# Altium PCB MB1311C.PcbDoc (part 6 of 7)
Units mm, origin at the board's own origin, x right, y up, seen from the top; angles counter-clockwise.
Board outline 100.03 x 67.03 mm, 6 copper layers (Top Layer, layer2, layer3, layer4, layer5, Bottom Layer), stack 1.208 mm thick; 366 components, 356 nets, 1582 pads, 964 vias.
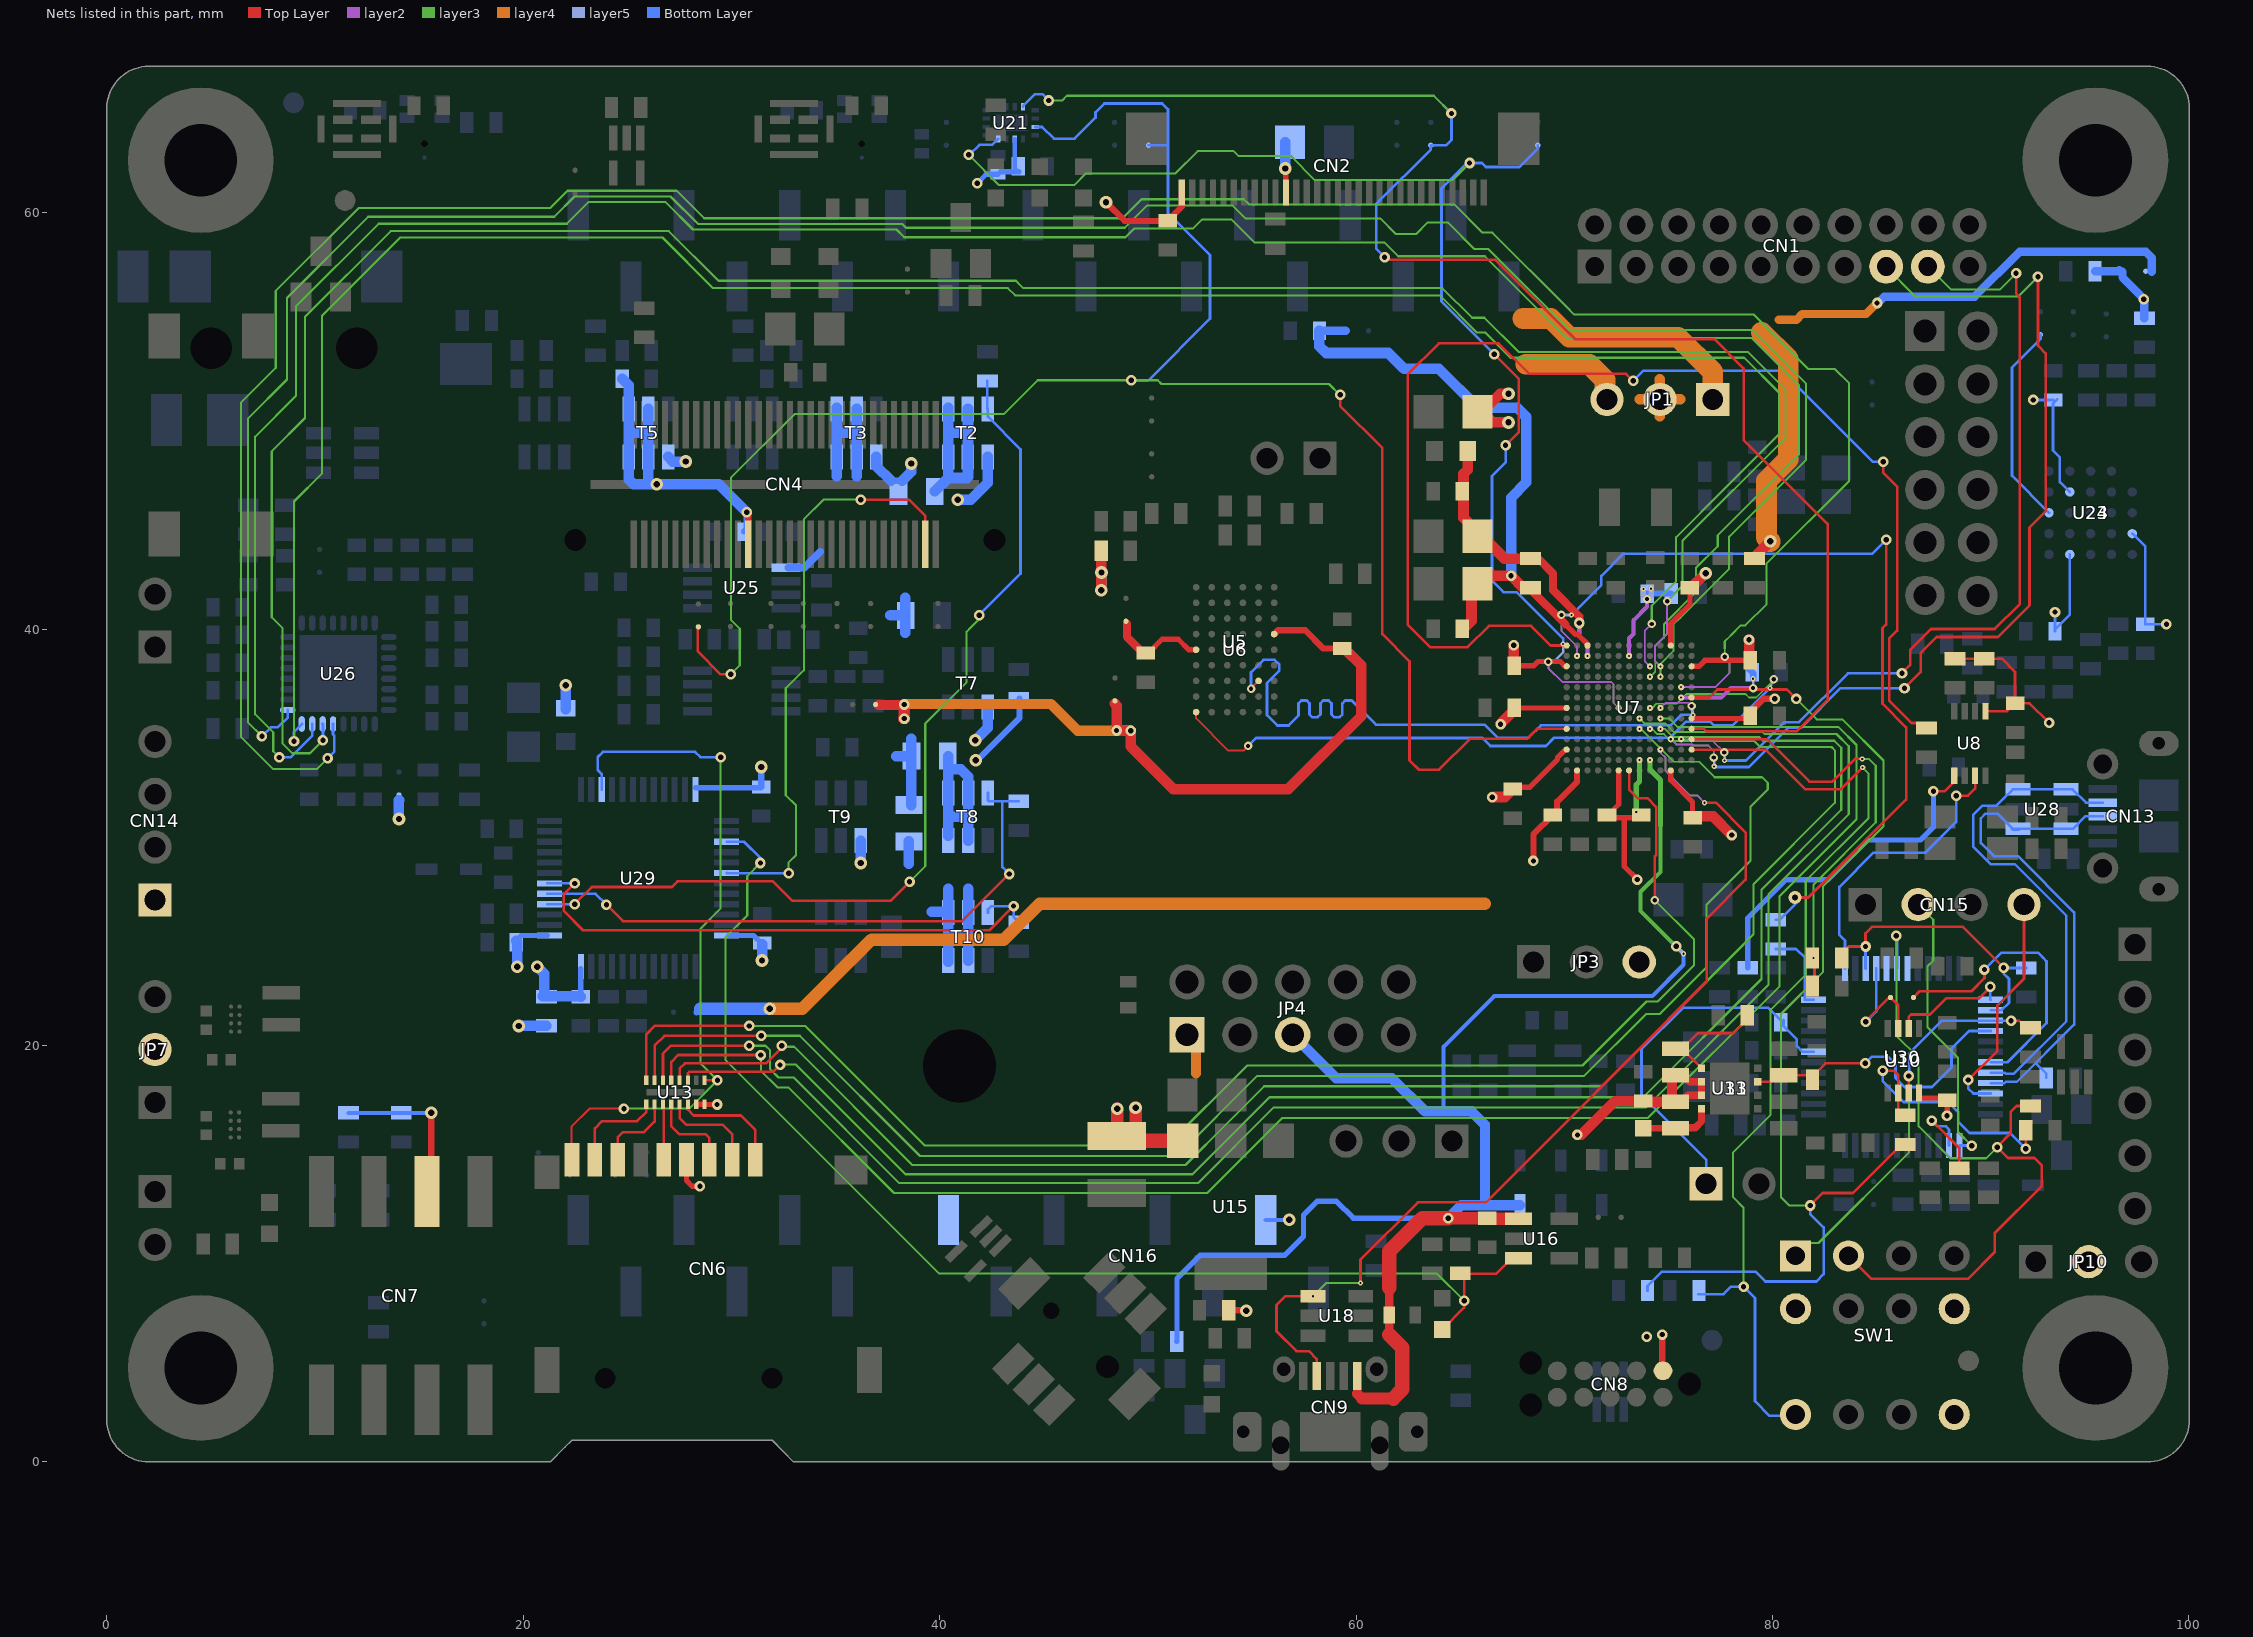
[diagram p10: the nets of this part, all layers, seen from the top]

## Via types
v1: diameter 0.508, hole 0.254, Top Layer to Bottom Layer, tented both sides, 462 vias
v2: diameter 0.61, hole 0.305, Top Layer to Bottom Layer, tented both sides, 126 vias
v3: diameter 0.406, hole 0.203, layer2 to layer5, tented both sides, 109 vias
v4: diameter 0.25, hole 0.1, Top Layer to layer2, tented both sides, 80 vias
v5: diameter 0.25, hole 0.1, Top Layer to layer3, tented both sides, 78 vias
v6: diameter 0.25, hole 0.1, layer5 to Bottom Layer, tented both sides, 52 vias
v7: diameter 0.406, hole 0.203, Top Layer to Bottom Layer, tented both sides, 48 vias
v8: diameter 0.508, hole 0.254, layer2 to layer5, tented both sides, 4 vias
v9: diameter 0.406, hole 0.203, layer2 to layer5, 3 vias
v10: diameter 0.25, hole 0.1, layer5 to Bottom Layer, tented bottom, 1 vias
v11: diameter 0.25, hole 0.1, Top Layer to layer3, tented top, 1 vias

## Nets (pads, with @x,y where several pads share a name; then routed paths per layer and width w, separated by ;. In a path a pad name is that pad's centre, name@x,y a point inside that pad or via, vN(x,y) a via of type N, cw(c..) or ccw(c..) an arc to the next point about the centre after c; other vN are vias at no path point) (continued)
PSRAM_WAIT: U6.J1 U7.E7 | length 37.3
  Top Layer w0.102: U6.J1@52.319,36.008 52.319,35.71 53.867,34.162 54.594,34.162 v7(54.816,34.384)
  layer3 w0.088: v5(74.117,36.208) v5@74.214,36.208 ; v5@74.22,36.202 74.429,36.411 75.4,36.411 75.875,36.886 78.7,36.886 78.875,36.711 79.221,36.711 v3@80.083,37.573
  layer5 w0.127: v6(79.878,37.165) v3(80.068,37.588)
  Bottom Layer w0.127: v7(54.816,34.384) 55.2,34.768 66.064,34.768 66.448,34.384 69.116,34.384 69.51,34.778 75.074,34.778 75.847,35.551 77.008,35.551 77.177,35.381 78.094,35.381 v6(79.878,37.165)
PSRAM_WE: U5.G5 U6.G5 U7.D7 | length 33.1
  Top Layer w0.102: v7(54.959,37.128) 54.959,37.148 U5.G5@55.319,37.508
  layer2 w0.088: v4(74.617,36.208) 74.866,36.457 75.965,36.457 v3(76.118,36.304)
  layer5 w0.127: v3(76.118,36.304) v6(76.188,35.878)
  Bottom Layer w0.127: v7(54.959,37.128) 54.959,37.923 55.553,38.517 56.095,38.517 56.316,38.296 56.316,37.999 55.727,37.41 55.727,35.861 56.221,35.367 56.761,35.367 57.238,35.844 57.238,36.434 57.37,36.566 57.634,36.566 57.765,36.434 57.765,35.898 57.897,35.766 58.161,35.766 58.292,35.898 58.292,36.434 58.424,36.566 58.688,36.566 58.819,36.434 58.819,35.898 58.951,35.766 59.215,35.766 59.346,35.898 59.346,36.434 59.478,36.566 59.795,36.566 60.952,35.409 66.181,35.409 66.804,34.786 68.29,34.786 68.877,35.373 75.098,35.373 75.603,35.878 v6(76.188,35.878)
PWR_ENn: R29.2 U11.3 U30.28 U33.3 | length 14.9
  Top Layer w0.127: U33.3@79.293,18.258 79.908,18.258 80.25,18.6 U11.3@80.575,18.6 ; U11.3@80.318,18.568 U11.3@80.543,18.568 81.708,18.568 R29.2@81.923,18.353 81.923,18.523 82.543,19.143 v1(84.453,19.143)
  Bottom Layer w0.127: v1(84.453,19.143) 84.773,19.463 85.543,19.463 85.913,19.093 85.913,18.433 86.343,18.003 87.663,18.003 88.603,18.943 88.603,19.853 89.443,20.693 U30.28@90.483,20.693
SAI1_FSA: U7.D4 U26.1 | length 121.1
  layer3 w0.088: v5(74.617,37.708) 74.617,38.315 75.249,38.947 75.249,40.219 75.572,40.542
  layer3 w0.102: v1(7.453,34.851) 6.777,35.527 6.777,50.107 8.653,51.983 8.653,55.901 12.556,59.804 21.494,59.804 22.467,60.777 27.078,60.777 28.393,59.462 38.197,59.462 38.386,59.273 48.894,59.273 49.967,60.346 54.062,60.346 54.686,59.722 61.157,59.722 61.904,58.975 62.888,58.975 63.443,59.53 63.77,59.53 64.4,59.53 65.675,58.255 66.351,58.255 70.25,54.356 79.04,54.356 81.618,51.778 81.618,48.128 77.922,44.431 77.922,42.892 75.572,40.542
  Bottom Layer w0.127: v1(7.453,34.851) 7.881,35.279 8.21,35.279 8.693,35.761 U26.1@8.693,36.113
SAI1_MCKA: U7.D3 U26.30 | length 116.5
  layer2 w0.088: v4(74.617,38.208) 74.367,38.457 74.367,39.204 74.943,39.78 v3(74.943,41.339)
  layer3 w0.102: v1(10.383,34.653) 9.763,34.033 8.913,34.033 8.433,34.513 8.433,40.053 7.924,40.562 7.924,48.534 9.523,50.133 9.523,54.993 13.639,59.109 26.997,59.109 29.381,56.725 43.667,56.725 43.759,56.634 44.017,56.375 64.147,56.375 65.574,54.948 66.165,54.948 67.802,53.311 78.811,53.311 80.632,51.49 80.632,49.181 75.683,44.232 75.683,42.079 v3(74.943,41.339)
  Bottom Layer w0.127: U26.30@10.363,35.443 U26.30@10.368,35.438 10.383,35.423 v1(10.383,34.653)
SAI1_SCKA: U7.E4 U26.31 | length 121.1
  layer3 w0.088: v5(74.117,37.708) 74.128,37.708 74.373,37.953 74.373,39.165 74.785,39.577 74.785,40.22
  layer3 w0.102: v1(8.284,33.834) 7.994,34.124 7.994,34.398 7.994,35.039 7.123,35.91 7.123,49.233 9.083,51.193 9.083,55.492 13.056,59.465 22.09,59.465 23.131,60.506 26.841,60.506 28.158,59.189 37.93,59.189 38.301,58.818 48.926,58.818 49.337,59.229 52.162,59.229 52.608,59.675 54.015,59.675 55.133,58.557 61.373,58.557 62.027,57.903 66.191,57.903 70.125,53.969 79.016,53.969 81.274,51.711 81.274,48.4 77.375,44.501 77.375,43.979 76.324,42.928 76.324,41.759 74.785,40.22
  Bottom Layer w0.127: v1(8.284,33.834) 8.825,33.834 9.863,34.872 U26.31@9.863,35.438
SAI1_SDA: U7.E3 U26.32 | length 112.5
  layer2 w0.088: v4(74.117,38.208) 73.867,38.457 73.867,39.907 v3(74.206,40.247)
  layer3 w0.102: v1(8.993,34.613) 8.993,46.124 10.343,47.474 10.343,55.059 14.089,58.805 26.689,58.805 29.119,56.375 43.273,56.375 43.625,56.023 64.023,56.023 65.804,54.242 66.206,54.242 67.418,53.03 78.64,53.03 80.313,51.357 80.313,49.356 77.673,46.716 75.373,44.416 75.373,42.293 74.206,41.126 v3(74.206,40.247)
  Bottom Layer w0.127: v1(8.993,34.613) 8.993,35.053 9.373,35.433 U26.32@9.368,35.438 U26.32@9.363,35.443
SAI1_SDB: U7.B5 U26.29 | length 130.3
  layer2 w0.088: v4(75.617,37.208) 77.264,37.208 77.935,37.879 77.935,38.448 v3(77.712,38.672)
  layer3 w0.088: v3(77.712,38.672) 77.712,39.079 ; 77.712,39.403 77.998,39.689
  layer3 w0.102: v1(10.605,33.799) 10.078,33.272 8.001,33.272 6.442,34.831 6.442,50.872 8.113,52.543 8.113,56.239 12.097,60.223 21.297,60.223 22.125,61.051 27.37,61.051 28.694,59.727 48.785,59.727 49.698,60.64 54.616,60.64 54.862,60.394 64.717,60.394 66.072,59.039 66.546,59.039 70.082,55.503 70.486,55.099 79.117,55.099 81.733,52.483 83.002,52.483 83.681,51.804 83.681,47.11 79.722,43.151 79.722,41.195 78.701,40.174 78.483,40.174 77.998,39.689 ; 77.712,39.079 77.712,39.403
  Bottom Layer w0.127: v1(10.605,33.799) 10.931,34.125 10.931,34.874 10.863,34.942 U26.29@10.863,35.443
SD_CLK: CN6.5 U13.11 | length 2.7
  Top Layer w0.127: U13.11@26.738,17.213 26.743,17.208 CN6.5@26.743,14.513
SD_CMD: CN6.3 U13.12 | length 4.2
  Top Layer w0.127: U13.12@27.113,17.172 27.113,16.113 27.488,15.738 28.763,15.738 28.943,15.558 CN6.3@28.943,14.513
SD_D0: CN6.7 U13.10 | length 4
  Top Layer w0.127: CN6.7@24.543,14.513 24.543,15.593 24.788,15.838 25.813,15.838 26.313,16.338 U13.10@26.313,17.172 U13.10@26.313,17.213
SD_D1: CN6.8 U13.9 | length 4.7
  Top Layer w0.127: CN6.8@23.443,14.513 23.443,16.018 23.788,16.363 25.473,16.363 25.913,16.803 U13.9@25.913,17.172
SD_D2: CN6.1 U13.14 | length 5.3
  Top Layer w0.127: U13.14@27.913,17.172 27.913,16.913 28.188,16.638 30.463,16.638 31.143,15.958 CN6.1@31.143,14.513
SD_D3: CN6.2 U13.13 | length 4.8
  Top Layer w0.127: U13.13@27.513,17.172 U13.13@27.513,17.163 ; U13.13@27.538,17.188 U13.13@27.513,17.163 ; CN6.2@30.043,14.513 30.043,15.733 29.588,16.188 27.838,16.188 27.513,16.513 U13.13@27.513,17.163
SH0: R49.2 T2.3 U29.4 | length 45.5
  Top Layer w0.127: v1(22.473,26.783) 23.301,27.611 27.141,27.611 27.413,27.883 31.993,27.883 32.933,26.943 37.643,26.943 v1(38.558,27.858)
  layer3 w0.102: v1(38.558,27.858) 39.313,28.613 39.313,35.463 41.3,37.45 41.3,39.875 41.499,40.074 41.903,40.479 v1(41.903,40.663)
  Bottom Layer w0.127: U29.4@21.171,26.783 v1(22.473,26.783) ; v1(41.903,40.663) 41.903,40.683 43.883,42.663 43.883,48.632 42.313,50.202 T2.3@42.313,50.573 42.293,50.593 R49.2@42.293,51.91
SH0_D: R55.2 T2.1 T2.2 T2.5 T2.6 | length 9.7
  Bottom Layer w0.127: T2.1@40.413,50.573 T2.1@40.413,50.623
  Bottom Layer w0.508: R55.2@39.772,46.613 40.413,47.254 ; T2.1@40.411,50.424 40.411,50.623 40.413,50.623 T2.1@40.413,50.573 40.413,49.44 ; T2.2@41.363,50.573 41.363,49.423 ; 40.413,47.254 41.295,47.254 41.363,47.322 T2.5@41.363,48.273 41.363,49.423 ; 40.413,47.254 40.413,49.44 ; 40.413,49.44 40.43,49.423 41.363,49.423
SH1: R84.2 T8.3 U29.5 | length 29.1
  Top Layer w0.127: v1(23.997,26.763) 24.792,25.968 41.078,25.968 v1(43.343,28.233)
  Bottom Layer w0.127: U29.5@21.171,27.283 23.477,27.283 v1(23.997,26.763) ; T8.3@42.323,32.136 42.323,31.783 42.383,31.723 43.013,31.723 ; v1(43.343,28.233) 43.013,28.563 43.013,31.723 ; R84.2@43.803,31.723 43.013,31.723
SH1_D: R81.2 T8.1 T8.2 T8.5 T8.6 | length 9.4
  Bottom Layer w0.508: R81.2@40.419,33.258 R81.2@40.421,33.258 ; T8.1@40.421,31.987 T8.1@40.421,32.186 ; R81.2@40.421,33.893 R81.2@40.421,33.258 ; T8.6@40.423,30.067 40.423,31.003 ; T8.2@41.371,31.937 41.371,32.904 41.017,33.258 R81.2@40.421,33.258 ; T8.5@41.373,29.836 41.373,30.986 ; T8.2@41.373,32.136 41.373,30.986 ; T8.1@40.421,32.186 R81.2@40.421,33.258 ; T8.1@40.421,32.186 40.423,32.186 T8.1@40.423,32.136 40.423,31.003 ; 40.423,31.003 40.44,30.986 41.373,30.986
SH2: R89.2 T10.3 U29.6 | length 27.6
  Top Layer w0.127: v1(22.473,27.783) 21.953,27.263 21.953,26.463 22.883,25.533 42.393,25.533 v1(43.553,26.693)
  Bottom Layer w0.127: U29.6@21.171,27.783 v1(22.473,27.783) ; T10.3@42.323,26.376 42.323,26.533 42.483,26.693 v1(43.553,26.693) 43.563,26.683 43.563,26.153 R89.2@43.803,25.913
SH2_D: R85.2 T10.1 T10.2 T10.5 T10.6 | length 10.2
  Bottom Layer w0.5: 38.523,28.713 R85.2@38.523,29.798
  Bottom Layer w0.508: 39.613,26.426 T10.1@40.421,26.426 ; T10.1@40.421,26.227 T10.1@40.421,26.426 ; 40.421,27.513 T10.1@40.421,26.426 ; T10.6@40.423,24.026 40.423,25.263 ; T10.2@41.371,26.177 41.371,27.513 ; T10.5@41.373,24.076 41.373,25.263 ; T10.2@41.373,26.376 41.373,25.263 ; T10.1@40.421,26.426 40.423,26.426 T10.1@40.423,26.376 40.423,25.263 ; 40.423,25.263 41.373,25.263
SPI2_MISOs: CN1.9 U7.B10 | length 41.8
  Top Layer w0.127: v1(86.223,37.879) 86.613,38.269 86.613,39.003 87.613,40.003 90.674,40.003 91.882,41.211 91.882,55.934 91.703,56.113 v1(91.703,57.093)
  layer2 w0.088: v4(75.621,34.709) 76.186,34.709 76.281,34.614 77.147,34.614 v3(77.686,34.074)
  layer3 w0.102: CN1.9@87.463,57.813 87.463,57.424 88.587,56.3 90.91,56.3 v1(91.703,57.093)
  layer5 w0.127: v3(77.686,34.074) v6(77.703,33.683)
  Bottom Layer w0.127: v6(77.703,33.683) 78.73,33.683 80.57,35.524 81.285,35.524 83.633,37.871 v1@86.231,37.871
SPI2_MOSIs: CN1.8 U7.C10 | length 46.9
  Top Layer w0.127: v1(86.343,37.159) 87.123,37.939 87.123,38.849 87.888,39.614 90.824,39.614 92.35,41.14 92.35,44.876 93.123,45.649 93.123,53.243 92.753,53.613 v1(92.753,56.913)
  layer2 w0.088: v4(75.117,34.708) 75.122,34.708 75.373,34.457 76.159,34.457 76.217,34.399 76.929,34.399 77.178,34.15 v3(77.178,33.828)
  layer3 w0.102: CN1.8@85.463,57.813 CN1.8@85.463,57.407 85.463,57.37 86.859,55.974 91.814,55.974 v1(92.753,56.913)
  layer5 w0.127: v3(77.178,33.828) v6(77.201,33.406)
  Bottom Layer w0.127: v6(77.201,33.406) 77.234,33.373 78.863,33.373 80.76,35.27 81.39,35.27 83.28,37.159 v1(86.343,37.159)
STL_USB_D_N: CN13.2 U28.1 U28.6 U30.32 | length 24.1
  Bottom Layer w0.122: U30.32@90.483,18.693 91.144,18.693 91.206,18.631 91.588,18.631 94.113,21.156 94.113,26.238 91.638,28.713 90.481,28.713 89.637,29.557 89.637,31.069 90.082,31.514 90.764,31.514 91.128,31.878 91.553,32.303 U28.6@91.803,32.303
  Bottom Layer w0.127: U28.6@91.803,32.303 U28.1@94.103,32.303 94.423,32.303 95.063,31.663 CN13.2@95.863,31.663
STL_USB_D_P: CN13.3 R98.2 U28.3 U28.4 U30.33 | length 25.6
  Bottom Layer w0.122: U30.33@90.483,18.193 91.144,18.193 91.206,18.255 91.744,18.255 94.489,21 94.489,26.394 91.794,29.089 90.637,29.089 90.013,29.713 90.013,30.913 90.238,31.138 90.813,31.138 91.128,30.823 91.548,30.403 U28.4@91.803,30.403 ; 92.659,19.134 93.153,18.64 R98.2@93.153,18.443
  Bottom Layer w0.127: U28.4@91.753,30.403 91.498,30.403 91.538,30.363 U28.4@91.838,30.363 ; U28.4@91.803,30.403 U28.3@94.103,30.403 94.428,30.403 95.038,31.013 CN13.3@95.863,31.013
STLINK_RX: U8.7 U30.13 | length 13.9
  Top Layer w0.127: v1(88.823,31.993) 89.393,31.993 89.733,32.333 U8.7@89.733,32.953
  Bottom Layer w0.127: U30.13@83.483,23.693 83.483,25.043 83.213,25.313 83.213,27.613 84.863,29.263 87.363,29.263 88.823,30.723 v1(88.823,31.993)
STLINK_TX: R88.1 U30.12 | length 4
  Bottom Layer w0.127: R88.1@80.163,24.633 81.133,24.633 81.553,24.213 81.553,22.193 U30.12@81.983,22.193
STM_JTCK: CN15.2 U30.37 | length 13.5
  layer3 w0.102: CN15.2@87.003,26.763 87.723,26.043 87.723,24.073 87.443,23.793 87.443,20.883 88.913,19.413 88.913,15.843 v1(89.573,15.183)
  Bottom Layer w0.127: U30.37@88.983,15.193 89.563,15.193 v1(89.573,15.183)
STM_JTMS: CN15.4 U30.34 | length 11.1
  Top Layer w0.127: v1(89.403,18.343) 90.803,19.743 90.803,21.923 92.083,23.203 CN15.4@92.083,26.763
  Bottom Layer w0.127: v1(89.403,18.343) 89.403,17.943 89.653,17.693 U30.34@90.483,17.693
STM_RST: C92.1 JP8.1 U30.7 | length 18
  Bottom Layer w0.127: JP8.1@76.813,13.353 76.813,14.513 73.713,17.613 73.713,19.823 75.693,21.803 79.803,21.803 C92.1@80.403,21.203 ; C92.1@80.533,21.223 80.533,20.933 81.173,20.293 81.173,19.973 81.453,19.693 U30.7@81.983,19.693
SWCLK: R24.1 R26.2 U7.A10 | length 22.2
  Top Layer w0.127: U7.A10@76.117,34.708 79.735,34.708 81.771,32.673 82.879,32.673 83.97,33.763 v5(84.313,33.763) ; R24.1@81.923,24.193 v5(81.973,24.193) ; R26.2@82.023,22.853 R24.1@82.023,24.233
  layer3 w0.102: v5(81.973,24.193) 81.973,27.723 84.963,30.713 84.963,33.433 84.633,33.763 v5(84.313,33.763)
SWDIO: R110.2 SW1.8 U7.A11 | length 47.6
  Top Layer w0.127: U7.A11@76.117,34.208 79.678,34.208 81.574,32.312 83.302,32.312 v5(84.333,33.343)
  layer3 w0.102: v1(78.613,8.413) 78.613,12.213 78.113,12.713 78.113,14.863 79.913,16.663 79.913,21.713 81.603,23.403 81.603,27.903 84.623,30.923 84.623,33.053 v5(84.333,33.343)
  Bottom Layer w0.127: R110.2@76.443,8.053 77.653,8.053 78.013,8.413 v1(78.613,8.413) 79.16,7.866 79.16,2.915 79.862,2.213 SW1.8@81.088,2.213
SWO: R31.1 R111.2 U7.A6 | length 54
  Top Layer w0.127: U7.A6@76.117,36.708 76.967,36.708 77.356,37.097 80.688,37.097 v1(81.143,36.643) ; v1(81.813,12.313) 82.413,12.913 83.863,12.913 86.193,15.243 R31.1@86.383,15.243
  layer3 w0.102: v1(81.143,36.643) 82.125,35.661 83.355,35.661 85.333,33.683 85.333,30.533 82.423,27.623 82.423,23.523 80.413,21.513 80.413,12.713 80.813,12.313 v1(81.813,12.313)
  Bottom Layer w0.127: R111.2@74.003,8.223 74.003,8.443 74.683,9.123 79.203,9.123 79.663,8.663 82.113,8.663 82.463,9.013 82.463,11.263 81.813,11.913 v1(81.813,12.313)
SWO_MCU: R31.2 R32.2 U10.6 | length 13.1
  Top Layer w0.127: v1(85.293,18.793) 85.823,18.793 86.043,18.573 U10.6@86.043,17.713 R31.2@86.043,16.643 ; R31.2@86.043,16.553 R31.2@86.043,16.643 ; R31.2@86.383,16.643 R31.2@86.043,16.643 ; v1(92.173,15.033) R32.2@92.173,15.923
  Bottom Layer w0.127: v1(85.293,18.793) 85.293,18.283 86.293,17.283 88.443,17.283 88.923,16.803 88.923,16.343 89.473,15.793 91.413,15.793 v1(92.173,15.033)
T50_4: JP1.1 R55.1 T3.4 | length 14.5
  layer4 w1: 68.013,54.913 69.35,54.913 70.252,54.011 75.465,54.011 77.137,52.339 JP1.1@77.137,51.027
  Bottom Layer w0.3: R55.1@37.667,47.123 R55.1@38.203,47.123
  Bottom Layer w0.5: T3.4@36.963,48.273 36.963,47.827 R55.1@37.667,47.123 ; R55.1@38.203,47.123 38.638,47.558 v2(38.638,47.951)
T50_6: R62.1 R81.1 R85.1 T3.1 T3.2 T3.5 T3.6 U25.5 | length 15.8
  Bottom Layer w0.356: U25.5@32.728,42.946 33.506,42.946 34.263,43.703
  Bottom Layer w0.508: T3.1@35.061,50.424 35.061,50.623 35.063,50.623 T3.1@35.063,50.573 35.063,49.44 ; 35.063,47.346 35.063,49.44 ; 36.013,47.346 T3.5@36.013,48.273 36.013,49.423 ; T3.2@36.013,50.573 36.013,49.423 ; 37.642,40.652 R62.1@38.354,40.652 ; 37.922,33.893 R81.1@38.634,33.893 ; 38.354,39.813 R62.1@38.354,40.652 ; 38.354,41.491 R62.1@38.354,40.652 ; R85.1@38.634,31.548 R81.1@38.634,33.893 ; 38.634,34.732 R81.1@38.634,33.893 ; 35.063,49.44 35.08,49.423 36.013,49.423
T_JRST: U30.19
T_JTCK: R24.2 R94.2 U30.15 U30.26 | length 14.7
  Top Layer w0.127: R24.2@83.323,24.193 83.323,24.413 83.663,24.753 v1(84.473,24.753) 84.473,25.383 84.783,25.693 89.143,25.693 v1(91.103,23.733)
  Bottom Layer w0.127: v1(84.473,24.753) 84.473,23.703 U30.15@84.483,23.693 ; U30.26@90.483,21.693 91.013,21.693 91.363,22.043 91.363,23.203 91.103,23.463 v1(91.103,23.733) 91.113,23.723 R94.2@92.193,23.723
T_JTDI: U30.17
T_JTDO: SB14.2 U10.3 U30.16 | length 6.1
  Top Layer w0.127: v1(84.483,21.133) 84.483,21.183 85.603,22.303 SB14.2@85.673,22.303 86.043,21.933 U10.3@86.043,20.813
  Bottom Layer w0.127: v1(84.483,21.133) 84.983,21.633 U30.16@84.983,23.693
T_JTMS: R28.2 SW1.1 U10.7 U30.27 | length 19.7
  Top Layer w0.127: U10.7@86.543,17.713 86.553,17.723 v1(86.553,18.533) ; v1(91.463,21.183) 91.473,21.193 91.833,21.193 92.183,20.843 R28.2@92.393,20.843
  layer3 w0.102: SW1.1@81.113,9.893 81.733,10.513 82.213,10.513 86.553,14.853 v1(86.553,18.533)
  Bottom Layer w0.127: v1(86.553,18.533) 86.563,18.543 86.563,19.613 88.143,21.193 U30.27@90.483,21.193 91.453,21.193 v1(91.463,21.183)
T_NRST: R30.2 SW1.2 U30.18 | length 34.5
  Top Layer w0.127: SW1.2@83.653,9.893 84.753,8.793 89.403,8.793 90.678,10.068 90.678,10.988 92.943,13.253 92.943,14.233 92.583,14.593 91.313,14.593 v1(90.793,15.113) 90.793,15.133 91.443,15.783 91.443,16.813 91.723,17.093 R30.2@92.393,17.093
  layer3 w0.102: v1(85.953,25.273) 85.953,20.473 87.023,19.403 87.023,16.113 88.553,14.583 90.263,14.583 v1(90.793,15.113)
  Bottom Layer w0.127: v1(85.953,25.273) 85.983,25.243 U30.18@85.983,23.693
T_SWDIO_IN: U10.2 U30.25 | length 5.7
  Top Layer w0.127: U10.2@86.543,20.813 86.543,21.363 86.663,21.483 87.563,21.483 88.343,22.263 89.913,22.263 v1(90.463,22.813)
  Bottom Layer w0.127: v1(90.463,22.813) 90.463,22.193 U30.25@90.483,22.193
T_SWO: SB14.1 U30.31 | length 14.1
  Top Layer w0.127: SB14.1@86.773,22.303 87.073,22.603 89.553,22.603 90.183,23.233 v1(90.183,23.643)
  Bottom Layer w0.127: v1(90.183,23.643) 90.993,24.453 92.753,24.453 92.99,24.215 ; U30.31@90.483,19.193 91.283,19.193 93.163,21.073 93.163,24.038 92.988,24.213
TOUCH_INT: CN4.4 U29.30 | length 28.6
  Top Layer w0.127: v1(36.213,46.213) 38.53,46.213 39.313,45.43 CN4.4@39.313,44.073
  layer3 w0.102: v1(32.751,28.265) 32.751,28.791 33.107,29.147 33.107,31.522 32.613,32.016 32.613,37.153 33.48,38.02 33.48,45.267 34.426,46.213 v1(36.213,46.213)
  Bottom Layer w0.127: U29.30@29.771,28.283 29.789,28.265 v1(32.751,28.265)
U5V_ST_LINK: C35.2 JP4.1 U11.6 U11.7 U33.6 U33.7 | length 12.6
  Top Layer w0.35: U11.7@75.175,17.3 75.568,17.3 75.65,17.3 75.958,17.608 U33.7@76.593,17.608 U33.6@76.593,18.258 76.017,18.258 75.675,18.6 U11.6@75.175,18.6
  Top Layer w0.5: v1(70.633,15.703) 70.813,15.703 72.443,17.333 C35.2@73.803,17.333 ; C35.2@73.838,17.298 U11.7@75.343,17.298 75.568,17.298 U11.7@75.568,17.3 ; U11.7@75.175,17.3 U11.6@75.175,18.6
  layer4 w0.5: JP4.1@51.883,20.463 52.313,20.033 52.313,18.663
U11_5: R27.2 U11.5 U33.5 | length 5.4
  Top Layer w0.12: U11.5@75.55,19.775 U11.5@75.726,19.775
  Top Layer w0.127: U11.5@75.568,19.838 75.663,19.838 76.424,20.599 78.139,20.599 78.798,21.258 R27.2@78.798,21.452
  Top Layer w0.13: U11.5@75.726,19.775 U33.5@76.593,18.908
U11_8: LD5.2 U11.8 U33.8 | length 3.7
  Top Layer w0.3: LD5.2@73.798,16.028 U11.8@75.343,16.028 U11.8@75.568,16.028
  Top Layer w0.35: U11.8@75.35,16.05 76.3,16.05 76.593,16.343 U33.8@76.593,16.958
USART2_RX: R88.2 U7.M2 | length 41.5
  Top Layer w0.127: v2(81.083,27.103) 81.72,27.103 86.422,31.805 86.422,35.279 85.284,36.417 85.284,40.038 85.463,40.217 v1(85.463,44.283)
  layer2 w0.088: v3(69.863,40.675) 69.863,39.915 70.617,39.161 v4(70.617,38.708)
  layer5 w0.127: v3(69.863,40.675) 70.337,40.675 v6(70.341,40.679)
  Bottom Layer w0.127: v6(70.341,40.679) 71.783,42.121 71.783,42.55 72.855,43.622 84.802,43.622 v1(85.463,44.283) ; R88.2@80.163,26.033 80.343,26.033 81.083,26.773 v2(81.083,27.103)
USART2_TX: R20.1 U7.N1 | length 61.4
  Top Layer w0.127: U7.N1@70.117,39.208 69.348,39.208 68.403,40.153 66.378,40.153 65.352,39.127 63.563,39.127 62.478,40.212 62.478,52.217 63.984,53.723 66.853,53.723 68.322,52.254 72.976,52.254 v1(73.311,51.919) ; v1(85.326,48.03) 85.326,47.501 85.991,46.836 85.991,39.925 85.604,39.538 85.604,36.572 86.686,35.49 87.006,35.49 87.253,35.243 R20.1@87.403,35.243
  Bottom Layer w0.127: v1(73.311,51.919) 73.798,52.406 80.445,52.406 84.821,48.03 v1(85.326,48.03)
USART3_RTS: SB18.1 U7.A9 U21.12 | length 74.7
  Top Layer w0.127: v1(61.373,57.863) 61.505,57.731 66.704,57.731 70.512,53.923 77.216,53.923 78.62,52.519 78.62,49.071 80.526,47.165 82.649,45.042 82.649,36.583 81.155,35.089 76.824,35.089 76.705,35.208 U7.A9@76.117,35.208
  layer3 w0.102: v1(45.242,65.386) 45.885,65.386 46.114,65.615 63.731,65.615 v1(64.583,64.763)
  Bottom Layer w0.127: U21.12@44.013,65.088 44.013,65.123 44.579,65.689 44.939,65.689 v1(45.242,65.386) ; v1(61.373,57.863) 60.97,58.266 60.97,60.41 63.593,63.033 SB18.1@63.593,63.233 64.327,63.233 64.583,63.489 v1(64.583,64.763)
USART3_RX: SB16.1 U7.H7 U21.4 | length 66.1
  Top Layer w0.127: v1(66.637,53.2) 67.818,52.019 67.818,49.458 v1(67.183,48.823)
  layer2 w0.088: v3(69.238,38.423) 69.238,38.126 69.906,37.458 70.017,37.458 ; 70.322,37.458 70.017,37.458 ; v5(72.617,36.208) 72.366,36.458 72.366,37.339 72.247,37.457 70.018,37.457 70.017,37.458
  layer3 w0.102: v1(41.393,62.783) 42.856,61.32 46.46,61.32 47.017,61.877 51.314,61.877 52.392,62.955 54.12,62.955 54.35,62.725 56.858,62.725 58.021,61.562 64.631,61.562 v1@65.453,62.384
  layer5 w0.127: v3(69.238,38.423) 69.49,38.423 69.946,38.879 v6(69.946,39.282)
  Bottom Layer w0.127: v1(41.393,62.783) 41.443,62.783 41.913,63.253 42.528,63.253 U21.4@42.813,63.538 ; v1(66.637,53.2) 64.107,55.73 64.107,61.16 65.33,62.383 v1(65.453,62.383) 66.043,62.383 66.233,62.193 67.843,62.193 68.733,63.083 SB16.1@68.733,63.233 ; v1(67.183,48.823) 67.183,48.002 66.528,47.347 66.528,42.327 67.081,41.774 67.719,41.774 69.946,39.547 v6(69.946,39.282)
USART3_TX: SB13.2 SB20.1 U7.N9 U21.15 | length 96.4
  Top Layer w0.127: SB13.2@28.413,40.103 28.413,40.023 28.387,39.997 28.387,38.925 29.487,37.825 v1(29.965,37.825) ; v1(59.24,51.249) 59.24,50.708 61.261,48.687 61.261,39.755 62.567,38.449 62.567,33.695 63.013,33.249 63.994,33.249 65.473,34.728 68.214,34.728 68.694,35.208 U7.N9@70.117,35.208
  layer3 w0.102: v1(29.965,37.825) 30.403,38.263 30.403,40.013 29.973,40.443 29.973,45.303 29.973,47.263 33.031,50.321 43.086,50.321 44.713,51.948 v1(49.206,51.948) 50.48,51.948 50.658,51.77 58.702,51.77 59.223,51.249 v1(59.24,51.249)
  Bottom Layer w0.127: U21.15@44.588,64.113 44.926,64.113 45.485,63.554 46.477,63.554 47.487,64.564 47.487,64.814 47.915,65.242 50.691,65.242 50.973,64.96 50.973,63.233 ; v1(49.206,51.948) 50.028,51.948 52.99,54.91 52.99,57.956 50.973,59.973 50.973,63.233 ; SB20.1@50.033,63.233 50.973,63.233
USB_OTGFS_ID: CN9.4 U7.D11 U18.1 | length 46.5
  Top Layer w0.127: v5(57.927,7.956) 56.606,7.956 56.183,7.533 56.183,6.273 57.143,5.313 57.743,5.313 58.113,4.943 CN9.4@58.113,4.118 ; v11(60.213,8.588) 60.213,9.713 62.967,12.467 66.237,12.467 76.853,23.083 76.853,26.103 78.712,27.962 78.712,30.224 77.278,31.658 v4(76.738,31.658)
  layer2 w0.088: v4(74.617,34.208) 74.624,34.201 74.624,34.058 74.867,33.816 74.867,33.167 76.026,32.008 76.388,32.008 v4(76.738,31.658)
  layer3 w0.102: v5(57.927,7.956) 58.461,8.49 ; 58.463,8.488 58.563,8.588 v11(60.213,8.588)
USB_OTGFS_OVRCR: LD7.2 R39.2 U16.3 U29.27 | length 58.9
  Top Layer w0.127: LD7.2@64.147,6.357 65.197,7.407 v1(65.197,7.739) 65.197,8.839 R39.2@65.003,9.033 ; R39.2@65.003,9.053 R39.2@65.003,9.033 ; U16.3@67.8,9.776 67.476,9.776 66.733,9.033 R39.2@65.003,9.033
  layer3 w0.102: v1(31.393,28.763) 30.763,28.133 30.763,26.238 29.713,25.188 29.713,19.313 39.983,9.043 63.893,9.043 v1(65.197,7.739)
  Bottom Layer w0.127: U29.27@29.771,29.783 30.611,29.783 31.393,29.001 v1(31.393,28.763)
USB_OTGFS_VBUS: C43.1 CN9.1 D2.1 D6.1 JP4.5 R113.1 U7.E12 U16.1 | length 81.7
  Top Layer w0.203: C43.1@66.303,11.703 C43.1@66.33,11.676
  Top Layer w0.4: 60.063,3.273 CN9.1@60.063,4.118 ; 61.593,8.369 61.598,8.364 D2.1@61.598,7.057 61.598,6.107
  Top Layer w0.5: 60.063,3.273 60.293,3.043
  Top Layer w0.6: 60.293,3.043 61.783,3.043 ; v1(64.423,11.703) C43.1@66.303,11.703 ; C43.1@66.33,11.676 U16.1@67.8,11.676
  Top Layer w0.7: 61.593,8.369 61.593,10.113 63.183,11.703 v1(64.423,11.703) ; 61.598,6.107 62.223,5.482 62.223,3.483 61.783,3.043
  layer3 w0.203: 74.618,30.566 74.618,28.335 73.665,27.382 73.665,26.455 75.361,24.759 v8(75.376,24.759)
  layer3 w0.25: v5(74.117,33.708) 74.117,33.247 74.618,32.746 74.618,30.566
  layer5 w0.203: v8(75.376,24.759) 75.731,24.403 v6(75.733,24.403)
  Bottom Layer w0.203: 64.203,16.833 64.203,19.933 66.643,22.373 74.233,22.373 75.733,23.873 v6(75.733,24.403) ; 66.063,12.333 66.193,12.333
  Bottom Layer w0.254: R113.1@51.388,5.788 51.401,5.801 51.401,8.811 52.51,9.92 56.57,9.92 57.478,10.828 57.478,11.857 58.134,12.513 59.063,12.513 59.873,11.703 v1(64.423,11.703)
  Bottom Layer w0.5: JP4.5@56.963,20.513 59.053,18.423 61.723,18.423 63.313,16.833 64.203,16.833 65.543,16.833 66.193,16.183 66.193,12.333 D6.1@67.873,12.333 ; v1(64.423,11.703) 65.053,12.333 66.063,12.333
USB_RENUMn: R35.2 U30.38 | length 4.6
  Top Layer w0.127: v1(87.653,16.393) 88.973,15.073 R35.2@88.973,14.103
  Bottom Layer w0.127: v1(87.653,16.393) 87.933,16.113 88.333,16.113 88.483,15.963 U30.38@88.483,15.193
uSD_CLK: U7.F8 U13.6 | length 85.5
  Top Layer w0.127: U13.6@26.713,18.322 26.713,19.613 27.088,19.988 v1(30.863,19.988)
  layer3 w0.088: v5(73.617,35.708) 73.867,35.458 74.866,35.458 75.273,35.051 79.529,35.051 79.566,35.015
  layer3 w0.102: v1@30.838,19.938 30.888,19.988 31.638,19.988 31.863,19.763 31.863,18.863 32.263,18.463 32.988,18.463 38.063,13.388 52.408,13.388 56.033,17.013 73.913,17.013 79.813,22.913 79.813,27.261 83.663,31.111 83.663,34.373 83.079,34.957 79.624,34.957 79.566,35.015
uSD_CMD: U7.D8 U13.5 | length 84.6
  Top Layer w0.127: U13.5@27.113,18.322 27.113,19.213 27.438,19.538 v1(31.413,19.538)
  layer3 w0.088: v5(74.617,35.708) 75.036,35.708 75.457,35.287 79.598,35.287
  layer3 w0.102: v1@31.413,19.513 31.413,18.788 32.213,17.988 32.738,17.988 37.813,12.913 52.863,12.913 56.463,16.513 74.013,16.513 80.343,22.843 80.343,27.177 84.038,30.872 84.038,34.429 83.18,35.287 79.598,35.287
uSD_D0: U7.F9 U13.7 | length 75.8
  Top Layer w0.127: U13.7@26.313,18.322 26.313,19.138 26.313,19.988 26.788,20.463 v1(31.438,20.463)
  layer3 w0.088: v5(73.617,35.208) 73.68,35.208 75.264,33.624 76.486,33.624 76.9,33.21
  layer3 w0.102: v1(31.438,20.463) 33.288,20.463 39.061,14.69 51.41,14.69 55.258,18.538 70.958,18.538 73.933,21.513 74.593,21.513 76.833,23.753 76.833,26.761 78.955,28.883 78.955,31.474 79.776,32.295 79.776,32.609 79.506,32.879 77.23,32.879 76.9,33.21
uSD_D1: U7.G13 U13.8 | length 69.6
  Top Layer w0.127: U13.8@25.913,18.322 25.913,20.538 26.313,20.938 v1(30.863,20.938) ; U7.G13@73.117,33.208 73.117,32.289 73.526,31.88 74.001,31.88 74.419,31.462 74.419,29.145 74.352,29.078 v4(74.352,26.979)
  layer3 w0.102: v1(30.863,20.938) 33.538,20.938 39.283,15.193 50.923,15.193 54.768,19.038 68.932,19.038 68.934,19.04 70.88,19.04 73.953,22.113 74.493,22.113 76.231,23.851 76.231,25.1 v4(74.352,26.979)
  other v9: 74.352,26.979
uSD_D2: U7.D9 U13.3 | length 79.9
  Top Layer w0.127: U13.3@27.913,18.322 27.913,18.663 27.988,18.738 32.013,18.738 v1(32.338,19.063)
  layer3 w0.088: v5(74.617,35.208) 74.818,35.208 75.205,34.821 79.352,34.821
  layer3 w0.102: v1@32.313,19.063 v1(32.338,19.063) 32.363,19.088 33.088,19.088 38.363,13.813 52.143,13.813 55.843,17.513 73.793,17.513 79.473,23.193 79.473,27.483 83.306,31.316 83.306,34.299 82.972,34.633 79.54,34.633 79.352,34.821
uSD_D3: U7.E9 U13.4 | length 79.4
  Top Layer w0.127: U13.4@27.513,18.322 27.513,18.888 27.768,19.142 31.668,19.142 32.413,19.888 v1(32.413,19.979)
  layer3 w0.088: v5(74.117,35.208) 74.216,35.208 74.469,34.955 74.792,34.955 75.123,34.624 79.123,34.624
  layer3 w0.102: v1@32.413,19.988 32.463,19.938 33.013,19.938 38.691,14.26 51.81,14.26 53.845,16.295 55.589,18.039 71.799,18.039 78.153,24.393 79.093,25.333 79.093,27.743 83.001,31.651 83.001,31.811 83.001,34.172 82.839,34.335 79.412,34.335 79.123,34.624
uSD_Detect: CN6.9 U13.1 U29.15 | length 34.2
  Top Layer w0.102: CN6.9@22.343,14.513 22.313,14.543 22.313,16.088 23.188,16.963 v1(24.838,16.963)
  Top Layer w0.127: U13.1@28.713,18.322 v1(29.329,18.322)
  layer3 w0.102: v1@24.813,16.963 v1(24.838,16.963) 27.97,16.963 v1(29.329,18.322) 28.513,19.138 28.513,25.613 29.483,26.583 v1(29.483,33.843)
  Bottom Layer w0.127: U29.15@23.771,32.283 23.771,33.035 23.581,33.225 23.581,33.852 23.834,34.105 28.251,34.105 28.513,33.843 v1(29.483,33.843)
VDD: C3.1 C46.1 C47.1 CN2.20 CN2.30 CN6.4 CN7.5 CN8.1 CN16.2 JP7.2 R16.1 R42.1 R46.2 R74.2 R97.1 R99.1 R100.1 SB23.1 SB30.1 SW1.5 T5.4 T9.4 U13.15 U13.16 U21.2 | length 66.3
  Top Layer w0.25: CN6.4@27.843,14.513 27.843,13.508 28.113,13.238 v1(28.488,13.238) ; U13.15@28.313,17.172 28.704,17.172 28.713,17.163 v1(29.313,17.163)
  Top Layer w0.254: v2(56.607,62.118) 56.632,62.093 CN2.20@56.632,60.973
  Top Layer w0.3: CN7.5@15.583,12.983 v2(15.583,16.763) ; v2(47.993,60.503) 48.893,59.603 C3.1@50.953,59.603 51.632,60.282 CN2.30@51.632,60.973 ; R42.1@53.883,7.283 54.703,7.283 v2(54.723,7.263) ; v1(74.713,6.113) 74.713,4.543 74.813,4.443 CN8.1@74.743,4.373
  Top Layer w0.508: R16.1@79.134,43.447 v2(79.896,44.209)
  layer4 w0.2: 80.292,54.862 80.302,54.852
  layer4 w0.4: 80.302,54.852 81.152,54.852 81.431,55.131 84.5,55.131 v1(85.027,55.658)
  layer4 w1: 79.469,54.257 80.763,52.963 80.763,48.163 79.713,47.113 79.713,44.392 v2(79.896,44.209)
  Bottom Layer w0.127: R46.2@42.803,61.843 R46.2@42.923,61.963 ; C47.1@43.613,62.163 C47.1@43.813,61.963
  Bottom Layer w0.2: R100.1@11.613,16.763 R99.1@14.143,16.763 v2(15.583,16.763) ; C47.1@43.613,62.163 U21.2@43.613,63.538 ; CN16.2@55.662,11.615 56.775,11.615 v2(56.793,11.633) ; v1(85.027,55.658) 85.301,55.932 85.332,55.932
  Bottom Layer w0.25: v1(41.813,61.413) 42.243,61.843 R46.2@42.803,61.843 ; R46.2@42.923,61.963 C47.1@43.813,61.963
  Bottom Layer w0.3: v2@41.766,33.66 43.843,35.737 R74.2@43.843,36.653
  Bottom Layer w0.4: v1@85.038,55.638 85.332,55.932 85.363,55.963 89.713,55.963 91.863,58.113 97.938,58.113 98.213,57.838 98.213,57.163
  Bottom Layer w0.5: v2(19.783,20.933) 19.789,20.939 R97.1@21.113,20.939 ; T5.4@26.963,48.273 27.193,48.043 v2(27.803,48.043)
  Bottom Layer w0.508: v2(14.033,30.873) 14.033,31.766 14.034,31.767 ; v2(36.213,28.763) T9.4@36.213,29.836 ; v2(56.607,62.118) C46.1@56.607,63.386
  other v1: 73.963,6.013
  other v2: 41.733,33.693
VDD1: C83.1 C88.1 C89.1 C90.1 CN14.1 JP1.3 L6.1 R97.2 T2.4 T7.4 U29.1 U29.24 U29.36 U29.48 | length 25.6
  layer4 w1: 68.163,52.713 71.213,52.713 71.957,51.969 71.957,51.119 JP1.3@72.163,50.913
  Bottom Layer w0.254: C89.1@19.667,25.027 19.923,25.283 U29.1@21.171,25.283 ; C90.1@22.771,22.339 U29.48@22.771,23.683 ; U29.24@28.271,32.383 C83.1@31.41,32.383 ; U29.36@29.871,25.283 31.065,25.283 C88.1@31.49,24.858
  Bottom Layer w0.3: v2(31.433,33.373) 31.433,32.425 C83.1@31.442,32.416
  Bottom Layer w0.508: C89.1@19.667,25.027 19.713,24.982 v2(19.713,23.773) ; v2(20.672,23.779) 21.013,23.438 21.013,22.434 20.942,22.363 22.747,22.363 C90.1@22.771,22.339 ; L6.1@22.046,36.159 L6.1@22.046,36.197 v2(22.046,37.302) ; v2(31.473,24.083) 31.473,24.841 C88.1@31.49,24.858 ; v2(40.876,46.214) 41.504,46.214 42.313,47.023 T2.4@42.313,48.273 ; v2(41.709,34.653) 42.315,35.259 42.315,36.144 T7.4@42.316,36.145 ; T7.4@42.313,36.196 T7.4@42.316,36.193 ; T7.4@42.316,36.145 T7.4@42.316,36.193 ; T7.4@42.316,36.145 42.34,36.169 T7.4@42.316,36.193
VDD_LCD: C53.2 C100.2 CN4.38 R13.2 T5.1 T5.2 T5.5 T5.6 | length 21.4
  Top Layer w0.25: v2@47.763,42.703 v2(47.773,42.713)
  Top Layer w0.3: v1(30.733,45.603) 30.813,45.523 CN4.38@30.813,44.073 ; v2@47.763,42.723 v2(47.773,42.713)
  Top Layer w0.5: v2(47.763,41.863) v2@47.763,42.703 ; v2@47.763,42.723 R13.2@47.763,43.763
  Bottom Layer w0.127: T5.1@25.061,50.424 T5.1@25.061,50.623
  Bottom Layer w0.3: C53.2@30.613,44.683 30.733,44.803 v1(30.733,45.603)
  Bottom Layer w0.5: C100.2@24.75,52.025 25.063,51.712 25.063,50.623 T5.1@25.063,50.573 ; v2(26.413,46.946) 29.39,46.946 v1(30.733,45.603) ; v2(47.763,41.863) 47.773,41.873 v2(47.773,42.713)
  Bottom Layer w0.508: T5.1@25.061,50.623 25.063,50.623 T5.1@25.063,50.573 25.063,49.44 ; 26.013,46.958 T5.5@26.013,48.273 26.013,49.423 ; T5.2@26.013,50.573 26.013,49.423 ; v2(26.413,46.946) 25.314,46.946 25.063,47.197 25.063,49.44 ; 25.063,49.44 25.08,49.423 26.013,49.423
VDD_MCU: C6.1 C12.1 C17.1 C18.1 C20.1 C21.1 C23.1 C24.1 C26.1 C27.1 C28.1 C61.1 C72.1 JP1.2 JP3.3 R61.2 SB31.1 U7.A3 U7.A8 U7.B6 U7.C1 U7.C13 U7.F12 U7.G2 U7.H13 U7.M13 U7.N3 U7.N7 U7.N11 | length 102.4
  Top Layer w0.245: C26.1@71.974,30.939 72.617,31.582 U7.H13@72.617,33.208
  Top Layer w0.254: C20.1@67.656,36.208 U7.N7@70.117,36.208 ; C18.1@67.656,38.24 68.542,38.24 68.745,38.443 69.81,38.443 70.045,38.208 U7.N3@70.117,38.208 ; C23.1@67.704,32.398 68.339,32.398 69.674,33.733 69.674,33.837 70.033,34.196 U7.N11@70.089,34.196 ; C26.1@71.974,30.939 72.882,30.939 ; 72.882,30.942 72.882,30.939 ; v1(73.511,27.965) 72.882,28.594 72.882,30.939 ; C27.1@73.706,31.066 73.577,30.937 72.884,30.937 72.882,30.939 ; U7.C13@75.117,33.208 75.117,32.741 76.165,31.693 C28.1@76.165,31.001 ; U7.C1@75.117,39.208 75.117,40.268 76.038,41.189 C12.1@76.038,41.923 ; U7.A8@76.117,35.708 78.713,35.708 C21.1@78.88,35.827 ; U7.A3@76.117,38.208 76.467,38.208 76.753,38.494 C17.1@78.88,38.494
  Top Layer w0.3: v1@68.52,28.831 v1(68.52,28.862) 68.52,30.142 C24.1@69.444,31.066 ; C24.1@69.656,31.143 69.656,31.701 70.617,32.662 U7.M13@70.617,33.208 ; C21.1@78.88,35.827 78.88,35.94 79.593,36.653 v1(80.114,36.653)
  Top Layer w0.508: v1(66.549,31.916) 66.564,31.932 67.151,31.932 C23.1@67.532,32.313 ; v1(66.942,35.427) 66.942,35.446 67.656,36.16 C20.1@67.656,36.208 ; v2(67.323,49.924) 66.561,49.924 66.053,50.432 66.924,51.303 v2(67.323,51.303) ; v1(67.577,39.226) 67.577,38.319 C18.1@67.656,38.24 ; C12.1@76.038,41.923 v2(76.8,42.685) ; C28.1@76.165,31.001 77.148,31.001 v1(78.045,30.104) ; v1(78.873,39.483) 78.88,39.476 C17.1@78.88,38.494
  layer2 w0.203: v4(73.117,38.708) 73.117,39.555 73.324,39.763 73.324,40.418 73.978,41.072 v3(73.978,41.44) ; v4(75.617,36.708) 77.547,36.708 78.002,37.163 v3(79.073,37.163)
  layer3 w0.25: v5@73.463,31.217 73.463,32.524 73.617,32.677 v5(73.617,33.708)
  layer4 w0.508: 73.631,51.027 JP1.2@74.597,51.027 ; 74.597,50.222 JP1.2@74.597,51.027 ; 74.597,51.993 JP1.2@74.597,51.027 ; 75.563,51.027 JP1.2@74.597,51.027
  layer4 w0.6: v2(31.838,21.763) 33.413,21.763 36.733,25.083 43.083,25.083 44.813,26.813 66.192,26.813
  layer5 w0.127: v3(79.073,37.163) v6(79.073,37.613)
  layer5 w0.254: v6(73.8,41.923) 73.8,41.618 v3(73.978,41.44) 74.173,41.636 v6(74.173,41.933)
  Bottom Layer w0.3: SB31.1@28.323,21.593 28.493,21.763 ; C61.1@73.993,41.693 74.003,41.703 R61.2@75.133,41.703 ; v1(78.873,39.483) 78.873,38.073 C72.1@79.023,37.923 79.073,37.873 v6(79.073,37.613)
  Bottom Layer w0.6: 28.493,21.763 v2(31.838,21.763)
  other v5: 73.461,31.217
VDD_OCTOSPIFLASH: C49.1 C65.1 C66.1 R47.2 R48.2 SB23.2 U23.B4 U23.D1 U23.E4 U24.B4 U24.D1 U24.E4 | length 20.1
  Bottom Layer w0.127: v1@92.523,50.993 v1(92.533,51.003) C49.1@93.493,51.003 ; v1@93.553,40.833 v1(93.573,40.813) C66.1@93.573,39.893 ; C66.1@93.623,40.033 94.283,40.693 U23.E4@94.283,43.583 ; C49.1@93.673,51.033 93.473,50.833 93.473,48.573 93.803,48.243 93.803,47.063 U23.B4@94.283,46.583 ; U23.D1@97.283,44.583 97.913,43.953 C65.1@97.913,40.233 v1(98.923,40.233)
  Bottom Layer w0.4: R47.2@95.493,57.183 96.608,57.183 96.663,57.238 ; SB23.2@96.813,57.163 96.813,56.888 v1@97.863,55.838 ; v1(97.838,55.838) v1@97.863,55.838 ; R48.2@97.863,54.933 v1@97.863,55.838
VDD_STL: C19.1 C34.1 JP10.2 R18.2 R19.2 R92.2 U8.1 U8.5 U10.8 | length 26.9
  Top Layer w0.127: v1(87.733,32.203) 88.263,32.203 88.733,32.673 U8.5@88.733,32.953 ; R18.2@88.774,38.576 R19.2@90.171,38.576 91.02,38.576 91.653,37.943 C19.1@91.653,36.433 ; U8.1@90.233,36.053 91.273,36.053 C19.1@91.653,36.433 ; v1(93.288,35.501) 92.356,36.433 C19.1@91.653,36.433
  Top Layer w0.254: U10.8@87.043,17.683 87.043,17.483 87.033,17.473 88.283,17.473 C34.1@88.393,17.363 88.393,16.633 v1(88.383,16.623)
  Bottom Layer w0.254: R92.2@78.813,23.733 78.813,26.113 80.663,27.963 82.663,27.963 84.563,29.863 87.113,29.863 87.733,30.483 v1(87.733,32.203)
VDD_VCORE: C14.1 SB38.1 SB39.1 U5.D6 U6.D6 | length 37.5
  Top Layer w0.305: U5.D6@56.069,39.758 56.251,39.94 57.555,39.94 58.429,39.066 C14.1@59.349,39.066
  Top Layer w0.5: 37.075,36.35 38.275,36.35 38.275,35.725 v1@38.25,35.7 ; 48.4,36.425 48.5,36.325 v1(48.5,35.125) 48.512,35.113 v1(49.181,35.113) ; 49.179,34.36 v1@49.179,35.1
  Top Layer w0.508: 49.179,34.36 51.235,32.304 56.736,32.304 60.246,35.814 60.246,38.262 59.442,39.066 C14.1@59.349,39.066
  layer4 w0.5: v1@38.325,35.7 38.3,35.725 v1(38.3,36.375) 38.325,36.4 45.35,36.4 46.637,35.113 v1(49.181,35.113)
  other v1: 38.3,35.7
VDD_VDDQ: C16.1 SB5.1 U5.E1 U6.E1 | length 4.8
  Top Layer w0.254: C16.1@49.9,38.875 50.05,38.875 50.685,39.51 51.461,39.51 51.963,39.008 U5.E1@52.319,39.008
  Top Layer w0.4: 49,40.25 49,39.625 49.775,38.85 C16.1@49.9,38.85 C16.1@49.925,38.85
VDDA: C7.1 C8.1 L3.2 R14.2 U7.L2 | length 13.3
  Top Layer w0.381: R14.2@68.374,43.385 68.747,43.385 69.462,42.67 69.462,41.869 70.726,40.605 v1(70.726,40.289)
  Top Layer w0.508: L3.2@65.368,48.548 65.368,47.653 65.164,47.449 65.164,45.352 67.131,43.385 R14.2@68.374,43.385
  layer2 w0.203: v1(70.726,40.289) 70.726,39.663 71.117,39.272 v4(71.117,38.708)
VIN: C39.1 CN16.8 U15.3 | length 6.1
  Top Layer w0.6: C39.1@48.533,15.688 v2(48.533,16.963) ; C39.1@49.413,15.428 v2(49.413,17.013)
  Top Layer w0.7: C39.1@48.503,15.658 C39.1@48.533,15.688 ; C39.1@48.742,15.648 48.733,15.428 49.413,15.428 U15.3@51.683,15.428
VPP_OCTOSPIFLASH: SB26.1 U23.C5 U24.C5 | length 9.9
  Bottom Layer w0.127: SB26.1@92.873,54.133 92.873,53.933 91.503,52.563 91.503,47.363 U23.C5@93.283,45.583
VREF+: C13.1 C15.1 C48.1 R14.1 SB27.2 U7.L1 | length 30.5
  Top Layer w0.254: 70.068,40.219 70.542,39.745 70.651,39.745 U7.L1@71.124,39.272
  Top Layer w0.381: R14.1@68.338,41.949 70.068,40.219
  Top Layer w0.508: C15.1@65.164,40.018 65.545,40.399 65.545,41.669 66.494,42.618 66.553,42.559 v1(67.447,42.559) 68.021,41.985 R14.1@68.374,41.985
  Bottom Layer w0.4: C48.1@58.243,54.323 SB27.2@59.503,54.323
  Bottom Layer w0.508: C48.1@58.243,54.323 58.243,53.576 58.562,53.257 61.555,53.257 62.307,52.505 63.975,52.505 65.857,50.623 67.742,50.623 68.18,50.185 68.18,47.046 67.447,46.313 v1(67.447,42.559)
pads on no net: B2.7 B2.8 B2.NPTH1 B2.NPTH2 CN2.2 CN2.3 CN2.12 CN2.13 CN2.18 CN2.22 CN2.24 CN2.31 CN2.32 CN3.9 CN3.10 CN4.2 CN4.20 CN4.25 CN4.30 CN4.31 CN4.32 CN4.33 CN4.34 CN4.35 CN4.37 CN4.39 CN4.41 CN4.42 CN4.45 CN4.46 CN4.47 CN4.48 CN4.50 CN4.51 CN4.52 CN4.54 CN4.55 CN4.56 CN4.58 CN4.59 CN4.65 CN4.66 CN6.13 CN6.NPTH1 CN6.NPTH2 CN7.2 CN7.6 CN8.7 CN8.8 CN8.9 CN8.11 CN8.12 CN8.13 CN9.11 CN9.12 CN12.5 CN12.7 CN12.MT1 CN12.MT2 SB26.2 U1.6 U1.7 U1.8 U2.6 U2.7 U2.8 U5.E3 U6.E3 U6.J4 U6.J5 U6.J6 U8.6 U13.2 U18.5 U18.6 U19.6 U20.6 U21.8 U21.17 U23.A2 U23.A3 U23.B1 U23.B5 U24.A2 U24.A3 U24.B1 U24.B5 U26.19 U26.20 U26.23 U26.24 U29.10 U29.13 U29.14 U29.38 U30.4 U30.11 U30.14 U30.21 U30.22 U30.40 U30.41 U30.42 U30.43 U30.45 U30.46

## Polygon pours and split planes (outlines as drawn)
VDD1 on layer4 "VDD1_L04_P734" (solid, remove dead copper, pour order 734): 40.313,45.713 41.313,45.713 43.513,47.913 44.013,48.413 52.213,48.413 53.713,49.913 53.913,50.113 59.213,50.113 65.363,50.113 67.113,51.863 71.813,51.863 71.813,52.813 70.413,54.213 45.013,54.213 43.313,52.513 40.113,49.313 40.113,45.913
+3V3 on layer4 "+3V3_L04_P726" (solid, remove dead copper, pour order 726): 77.813,63.813 77.813,66.213 90.58,66.213 91.813,65.013 91.813,60.963 95.363,57.413 95.363,55.413 92.013,52.063 92.013,37.213 90.863,36.063 89.163,36.063 86.963,33.863 86.963,30.983 80.513,24.533 80.513,15.413 78.713,13.613 78.713,11.713 80.013,10.413 80.013,1.663 79.163,0.813 61.513,0.813 13.713,0.813 5.934,8.592 1.596,8.592 0.513,9.675 0.513,14.013 0.513,17.416 1.01,17.913 2.832,17.913 8.432,12.313 21.313,12.313 24.813,8.813 39.013,8.813 39.813,8.813 42.313,11.313 43.913,12.913 51.913,12.913 52.113,12.913 52.913,12.113 53.113,11.913 53.113,8.063 55.713,5.463 74.963,5.463 75.313,5.813 75.313,6.463 73.063,8.713 62.763,8.713 62.213,9.263 62.213,13.363 63.013,14.163 70.413,14.163 71.213,14.963 71.213,16.113 67.613,19.713 67.613,19.913 67.613,24.313 68.013,24.713 69.213,24.713 69.213,24.513 69.713,24.013 69.713,22.813 69.913,22.813 70.513,22.213 74.113,22.213 75.313,23.413 75.313,26.713 80.963,32.363 80.963,60.663
VDD_MCU on layer4 "VDD_MCU_L04_P690" (solid, remove dead copper, pour order 690): 67.213,51.663 71.713,51.663 72.813,52.763 79.213,52.763 80.713,51.263 80.713,32.379 75.013,26.779 75.013,23.513 74.016,22.516 69.61,22.516 65.413,26.713 65.413,49.863
+5V on layer4 "+5V_L04_P730" (solid, remove dead copper, pour order 730): 6.798,19.042 9.842,19.042 13.413,22.613 13.413,31.013 13.913,31.513 14.613,31.513 17.913,34.813 17.913,39.913 17.913,40.013 24.013,46.113 24.113,46.213 24.113,47.863 25.663,49.413 25.663,50.563 27.863,52.763 32.013,52.763 32.563,53.313 32.563,56.463 33.963,57.863 33.963,59.4 37.376,62.813 38.913,62.813 42.713,62.813 68.713,62.813 72.126,59.4 79.963,59.4 79.963,61.263 77.413,63.813 77.413,66.213 16.613,66.213 15.763,65.363 15.763,51.813 16.513,51.063 21.163,51.063 22.513,49.713 22.513,48.813 21.313,47.613 17.413,47.613 14.313,44.513 13.713,43.913 13.713,41.313 13.713,34.863 10.863,32.013 6.013,32.013 5.013,31.013 5.013,29.913 5.013,21.703 6.597,20.119 6.597,19.243
VDD on layer4 "VDD_L04_P728" (solid, remove dead copper, pour order 728): 72.913,8.413 75.013,6.313 75.013,5.913 74.813,5.713 55.854,5.713 53.413,8.154 53.413,11.613 53.413,12.013 52.113,13.313 43.613,13.313 42.513,12.213 39.513,9.213 38.913,9.213 24.863,9.213 21.495,12.581 8.52,12.581 2.838,18.263 1.012,18.263 0.531,18.744 0.531,20.897 0.947,21.313 5.073,21.313 6.366,20.02 6.366,19.235 6.723,18.878 9.878,18.878 11.313,20.313 13.613,22.613 13.613,30.963 13.963,31.313 14.713,31.313 17.913,34.513 18.113,34.713 18.113,39.013 18.113,39.913 24.313,46.113 24.313,46.813 24.313,47.763 25.863,49.313 25.863,50.463 27.963,52.563 31.963,52.563 32.713,53.313 32.713,56.413 34.138,57.838 34.138,59.363 37.388,62.613 67.813,62.613 68.324,62.613 73.965,56.763 80.563,56.763 80.563,53.713 80.163,53.313 71.457,53.313 68.192,56.513 36.413,56.513 35.813,55.913 35.813,51.613 31.713,47.513 26.213,47.513 25.863,47.163 25.863,45.813 27.163,44.513 27.163,38.739 26.467,38.013 24.613,38.013 22.013,38.013 21.213,37.213 21.213,37.013 21.213,31.913 18.963,29.663 18.963,21.963 19.513,21.413 19.613,21.313 21.313,21.313 21.613,21.313 23.813,23.513 31.613,23.513 32.313,24.213 32.313,24.613 32.313,30.413 35.913,34.013 42.013,34.013 42.363,33.663 42.363,26.363 41.563,25.563 36.513,25.563 33.113,22.163 33.113,21.313 33.249,21.313 35.106,19.456 49.67,19.456 51.713,17.413 58.613,17.413 60.413,15.613 61.913,14.113 61.913,9.213 62.713,8.413 63.813,8.413
VDD1 on layer4 "VDD1_L04_P712" (solid, remove dead copper, pour order 712): 19.813,21.613 19.213,22.213 19.213,28.013 19.213,29.613 20.213,30.613 21.413,31.813 21.413,37.163 22.063,37.813 23.513,37.813 41.113,37.813 42.313,36.613 42.313,34.613 41.913,34.213 37.213,34.213 35.613,34.213 32.433,31.033 32.013,30.613 32.013,24.013 31.713,23.713 24.113,23.713 23.613,23.713 21.513,21.613
VDD_LCD on layer4 "VDD_LCD_L04_P724" (solid, remove dead copper, pour order 724): 26.063,47.063 26.263,47.263 31.563,47.263 36.013,42.813 46.813,42.813 46.913,42.813 52.813,48.713 53.913,49.813 57.013,49.813 64.213,49.813 65.113,48.913 65.113,28.813 64.413,28.113 63.713,27.413 60.913,27.413 52.113,27.413 42.613,27.413 42.613,36.663 41.263,38.013 28.113,38.013 27.413,38.713 27.413,44.563 26.063,45.913
VDD_OCTOSPIFLASH on layer4 "VDD_OCTOSPIFLASH_L04_P700" (solid, remove dead copper, pour order 700): 98.413,56.613 96.913,56.613 92.213,51.913 92.213,50.613 92.213,39.713 92.613,39.313 97.813,39.313 99.013,39.313 99.363,39.663 99.363,55.663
